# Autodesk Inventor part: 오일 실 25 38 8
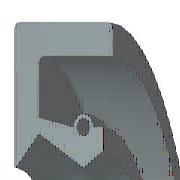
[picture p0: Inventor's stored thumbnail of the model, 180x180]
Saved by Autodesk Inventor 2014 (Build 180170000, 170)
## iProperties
Created: 2012-02
Part Number: 오일 실 25 38 8
Material: 고무
Description: 오일-실
Document SubType Name: Modeling
Standard: KS B 2804
Designer: mduedu
Standards Organization: KS
Language: ko-KR
Size Designation: D - 25 38 8
Categories: <MemberInstance><Categories><Category DisplayName="샤프트 부품" InternalName="7f7aeb1f-a693-4053-b835-cee3144e0d98" Mnemonic="SHFT"><Category DisplayName="실링" Intern
Density: 0.93 g/cm^3
Appearance: Rubber - Black - Version 1.1
Mass: 2.72583 g
Surface Area: 38.9868 cm^2
Volume: 2.931 cm^3
IsCustomPart: 1
Author: mduedu
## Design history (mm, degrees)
revolve "본체" stored, may be unused: angle "d17" = 90 deg
revolve "스프링1" stored, may be unused: angle "d18" = 90 deg
body "Solid1"
sketch "스케치1"
  geometry: L1 (0, 19)-(8, 19); L2 (8, 17.25)-(1.75, 17.25); L3 (1.75, 14.25)-(4.9, 12.5); L4 (4.9, 12.5)-(0, 12.5); L5 (0, 0)-(9.586, 0) reference; L6 (4.9, 12.5)-(6.3, 13.375); L7 (0, 18)-(0, -3) reference; L8 (-1.941, 0)-(11.507, 0) reference; L9 (4.2, 14.6)-(1.75, 15.21); L10 (1.75, 15.21)-(1.75, 17.25); L11 (0, 19)-(0, 12.588); L12 (4.9, 12.5)-(0, 12.5); L13 (1.75, 14.25)-(0.152, 12.528); L14 (8, 19)-(8, 17.25); L15 (5.6, 14.6)-(6.3, 14.6); L16 (6.3, 14.6)-(6.3, 13.375); C1 r 0.455 at (4.9, 14.6); A1 r 0.7 centre (4.9, 14.6) between (5.6, 14.6) and (4.2, 14.6); A2 r 0.088 centre (0.087, 12.588) between (0, 12.588) and (0.152, 12.528); 1 further point
  constraints: 28 end point, 5 horizontal alignment, 5 point on line, 4 point on circle, 4 vertical alignment, 3 centre point, 3 tangent, 2 collinear, 2 horizontal, 2 perpendicular, 1 coincident, 1 parallel
  dimensions: "d0" = 38 diameter of L1 L5 (= SD2); "d1" = 1.75 distance of L1.end L2.start (= SD); "d2" = 0.91 diameter of C1 (= SPDI); "d3" = 1.4 diameter of A1 (= SPDA); "d4" = 25 diameter of L3.end L5 (= NND); "d5" = 28.5 diameter of L3.start L5 (= TKDM); "d7" = 30.42 diameter of L9.end L5 (= TKDM + 0.24 x SWDT); "d8" = 1.75 distance between parallel lines of L11 L10 (= SD); "d9" = 4.9 distance from line of L11 C1.centre (= SPDST); "d10" = 29.2 diameter of C1.centre L5 (= HLDM); "d11" = 0.0875 radius of A2 (= 0.25 x LAB); "d12" = 6.3 distance between parallel lines of L11 L16 (= SDI); "d13" = 26.75 diameter of L6.end L5 (= ABDM); "d14" = 8 distance from line of L11 L1.end (= SWDT)
fillet "모깎기1" dims "d6" = 0.3 (= RR)
other parameters: "SD2" = 38 [user parameter; used in 1 equation term], "SWDT" = 8 [user parameter; used in 2 equation terms], "RR" = 0.3 [user parameter; used in 1 equation term], "SD" = 1.75 [user parameter; used in 2 equation terms], "NND" = 25 [user parameter; used in 1 equation term], "SPDA" = 1.4 [user parameter; used in 1 equation term], "SPDI" = 0.91 [user parameter; used in 1 equation term], "TKDM" = 28.5 [user parameter; used in 2 equation terms], "HLDM" = 29.2 [user parameter; used in 1 equation term], "ABDM" = 26.75 [user parameter; used in 1 equation term], "SDI" = 6.3 [user parameter; used in 1 equation term], "SPDST" = 4.9 [user parameter; used in 1 equation term], "LAB" = 0.35 [user parameter; used in 1 equation term], "d15" = 0, "d16" = 0, "d19" = 0
